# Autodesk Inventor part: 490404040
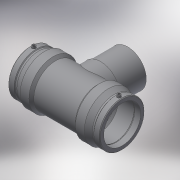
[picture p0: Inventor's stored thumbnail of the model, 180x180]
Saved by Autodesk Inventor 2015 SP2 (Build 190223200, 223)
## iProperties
Created: 2017-06
Part Number: 490404040
Material: Generic
Description: PLASSON TEE 40-40-40
Document SubType Name: Modeling
Designer: KIM
Mass: 164.139 g
Surface Area: 541.717 cm^2
Volume: 164.139 cm^3
Density: 1 g/cm^3
Appearance: Default
Author: KIM
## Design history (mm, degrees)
derived "490404.ipt"
feature "Solid1::490404.ipt"
tag "TaggingFeature1"
body "Solid1"
other parameters: "d2" = 56, "d3" = 43, "d5" = 50.4, "d6" = 38, "d8" = 168 deg, "d10" = 17.2, "d11" = 5.73333, "d14" = 17.6296, "d17" = 36, "d19" = 3.52592, "d20" = 168 deg, "d22" = 52.08, "d23" = 56, "d24" = 50.5176, "d25" = 135 deg, "d26" = 84, "d27" = 135 deg, "d29" = 47, "d30" = 15, "d31" = 48, "d34" = 5 deg, "d35" = 15, "d39" = 5 deg, "d40" = 9.6, "d41" = 4.8, "d42" = 6, "d43" = 0, "d45" = 4, "d46" = 14, "d47" = 0, "d51" = 0, "d52" = 32, "d54" = 0, "d55" = 50.4, "d56" = 56, "d57" = 42, "d58" = 135 deg, "d59" = 43, "d60" = 43, "d61" = 135 deg, "d72" = 54.6, "d73" = 27.3, "d75" = 42, "d77" = 0, "d78" = 32, "d80" = 0, "d82" = 62, "d83" = 0, "d84" = 3, "d85" = 0, "d86" = 3, "d87" = 0, "d88" = 12.47, "d89" = 3.1175, "d90" = 12.47, "L_1" = 43, "D_" = 56, "A_" = 47, "d_2" = 12
